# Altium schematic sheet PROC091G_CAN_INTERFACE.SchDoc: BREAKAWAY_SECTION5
size 431 x 279 mm; Date: Not shown in title block; ApprovedBy: Not shown in title block; CheckedBy: Not shown in title block; Author: Not shown in title block; CompanyName: Not shown in title block; DrawnBy: Antony/Bala; Engineer: Not shown in title block; Organization: Not shown in title block; Address1: Not shown in title block; Address2: Not shown in title block; Address3: Not shown in title block; Address4: Not shown in title block; DocumentNumber: 11; Revision: Use project parameter SCH_Rev; SheetNumber: 11; SheetTotal: 12; PageSetup: Record=PageOptions¦CenterHorizontal=True¦CenterVertical=True¦PrintScale=1.00¦XCorrection=1.00¦YCorrection=1.00¦PrintKind=0¦BorderSize=5000000¦LeftOffset=0¦BottomOffset=0¦Orientation=2¦PaperLength=1000¦PaperWidth=1000¦Scale=100¦PaperSource=15¦PrintQuality=600¦MediaType=1¦DitherType=10¦PaperKind=Letter¦PrintScaleMode=1
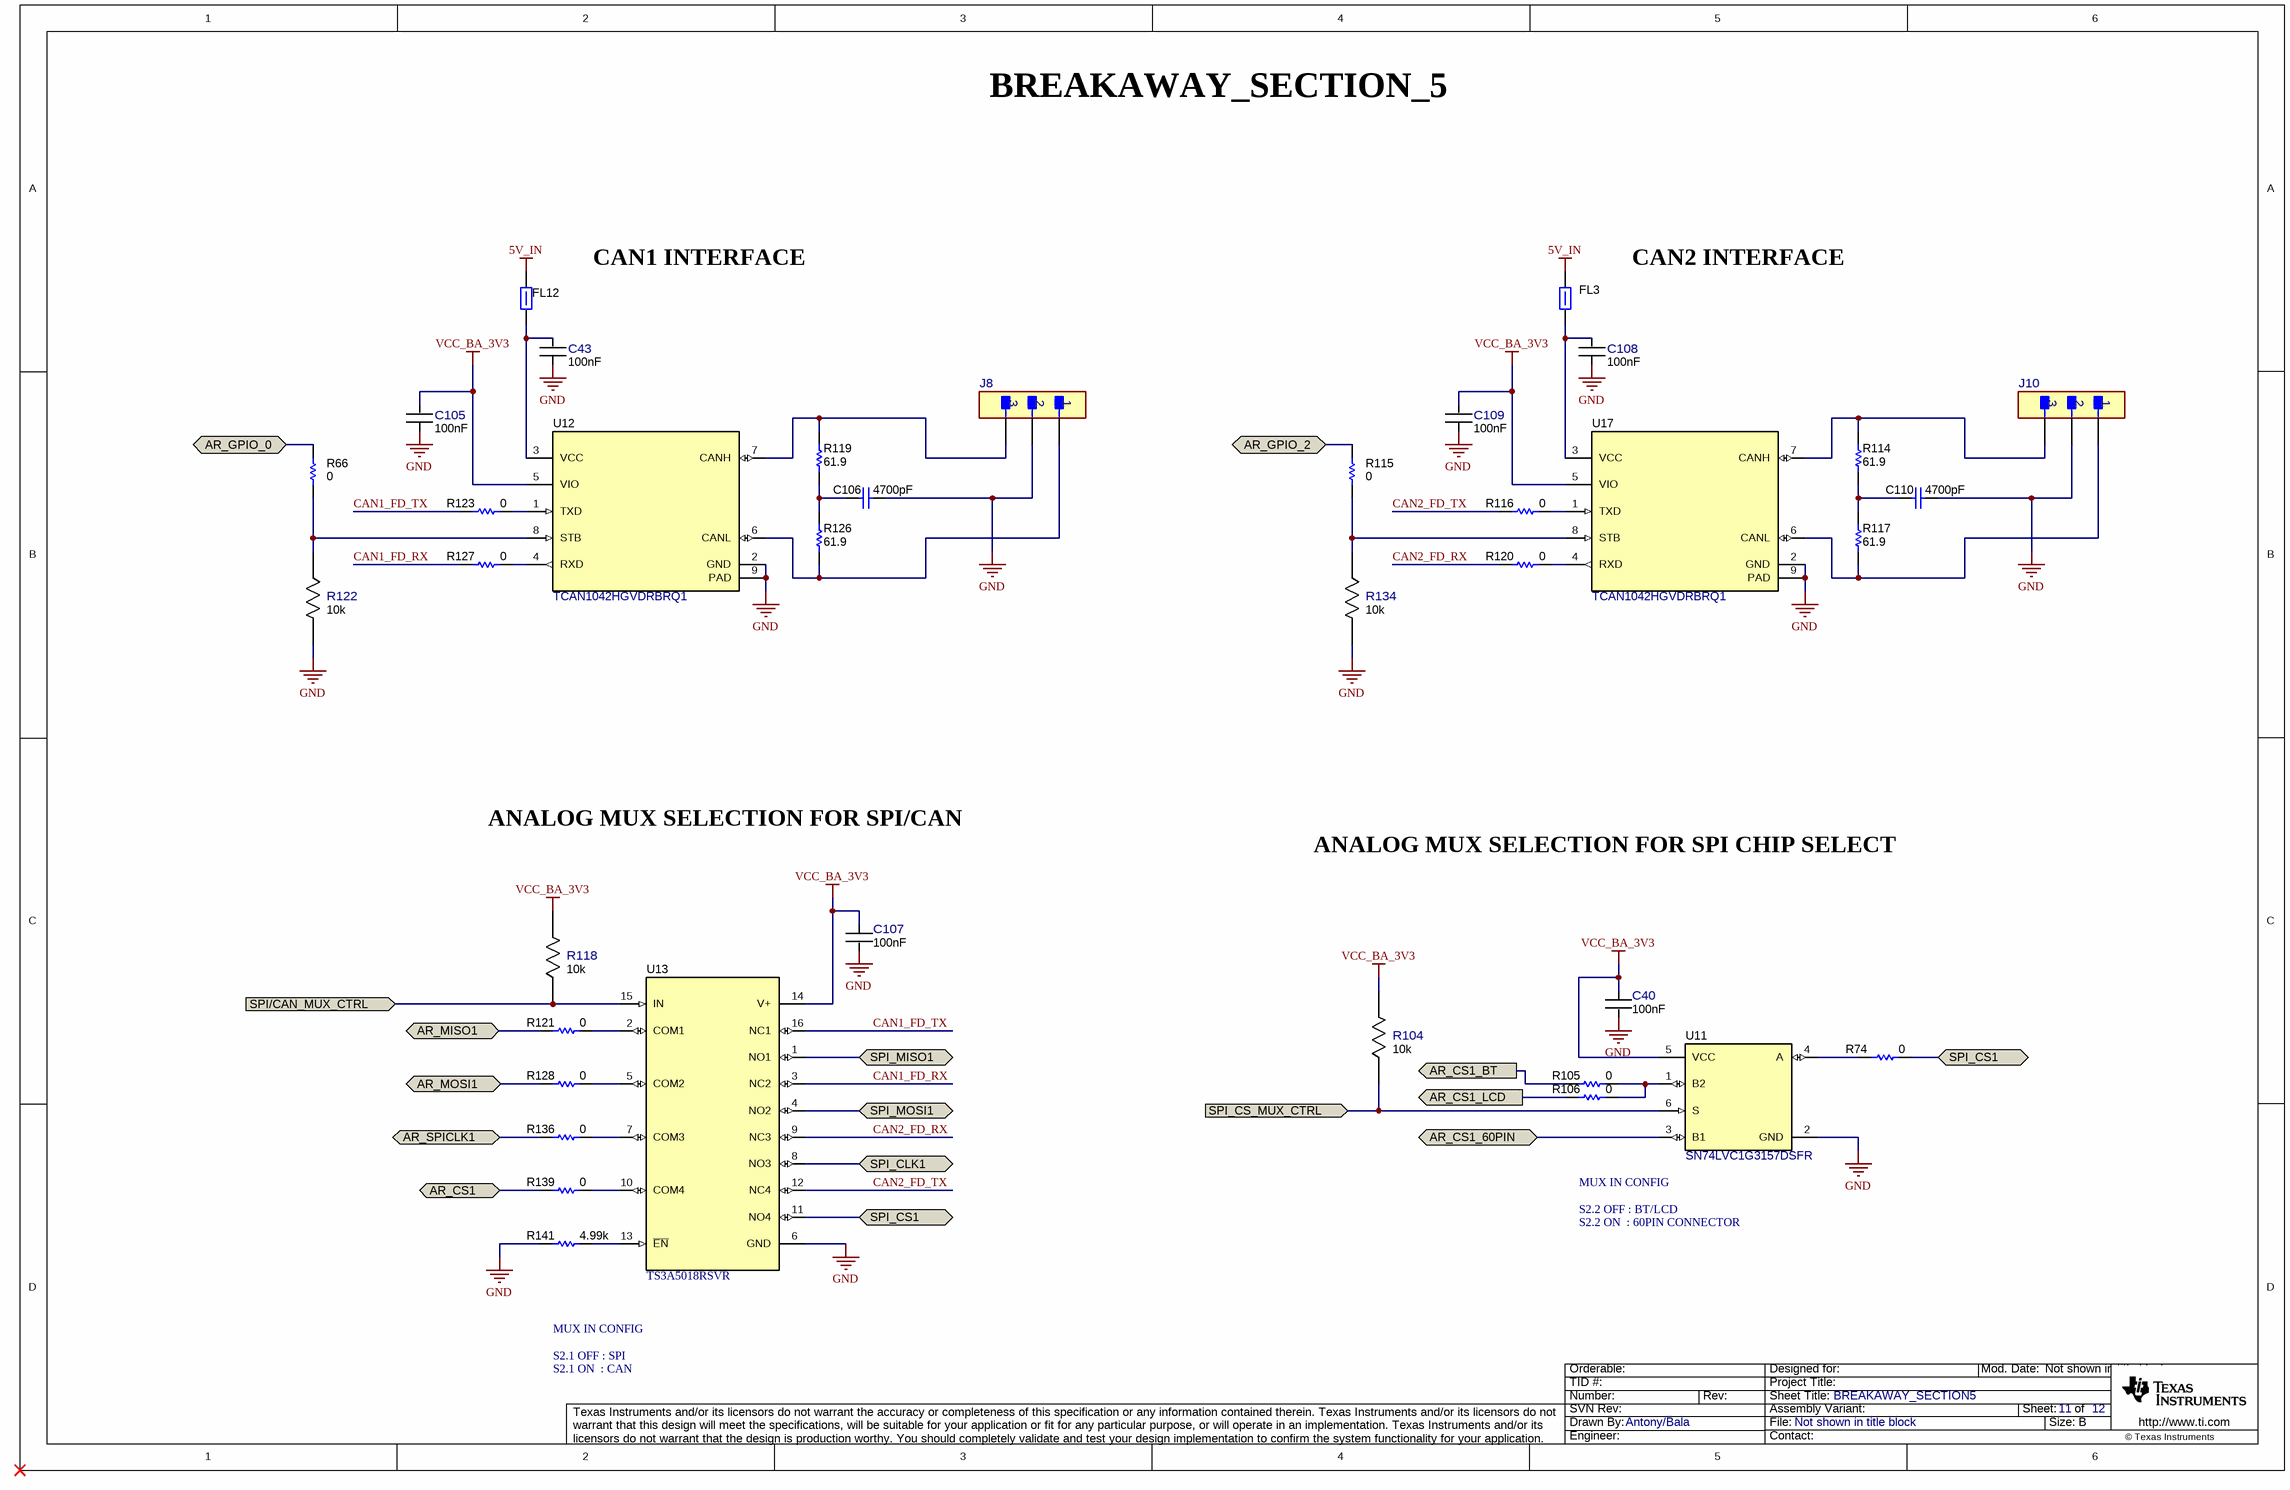
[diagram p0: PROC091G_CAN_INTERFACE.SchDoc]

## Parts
C40  Cap_F: 100nF  [FP-GRM033R6YA104KE14D_0201 (0603 Metric)-IPC_C]  (hidden comment: GRM033R6YA104KE14D)
C43  Cap_F: 100nF  [FP-GRM033R6YA104KE14D_0201 (0603 Metric)-IPC_C]  (hidden comment: GRM033R6YA104KE14D)
C105  Cap_F: 100nF  [FP-GRM033R6YA104KE14D_0201 (0603 Metric)-IPC_C]  (hidden comment: GRM033R6YA104KE14D)
C106  ValueDisplayed: 4700pF  [0402L]  (hidden comment: GRM155R71H472KA01D)
C107  Cap_F: 100nF  [FP-GRM033R6YA104KE14D_0201 (0603 Metric)-IPC_C]  (hidden comment: GRM033R6YA104KE14D)
C108  Cap_F: 100nF  [FP-GRM033R6YA104KE14D_0201 (0603 Metric)-IPC_C]  (hidden comment: GRM033R6YA104KE14D)
C109  Cap_F: 100nF  [FP-GRM033R6YA104KE14D_0201 (0603 Metric)-IPC_C]  (hidden comment: GRM033R6YA104KE14D)
C110  ValueDisplayed: 4700pF  [0402L]  (hidden comment: GRM155R71H472KA01D)
FL3  BLM15PD300SZ1D  [0402L]  (value not drawn)
FL12  BLM15PD300SZ1D  [0402L]  (value not drawn)
J8  M50-3930342  [FP-M50-3930342_HDR3-MFG]  (value not drawn)
J10  M50-3930342  [FP-M50-3930342_HDR3-MFG]  (value not drawn)
R66  Res_ohm: 0  [FP-RC0201JR-070RL_0201 (0603 Metric)-IPC_C]  (hidden comment: RC0201JR-070RL)
R74  Res_ohm: 0  [FP-RC0201JR-070RL_0201 (0603 Metric)-IPC_C]  (hidden comment: RC0201JR-070RL)
R104  Res_ohm: 10k  [FP-RR0306P-103-D_0201-IPC_C]  (hidden comment: RR0306P-103-D)
R105  Res_ohm: 0  [FP-RC0201JR-070RL_0201 (0603 Metric)-IPC_C]  (hidden comment: RC0201JR-070RL)
R106  Res_ohm: 0  [FP-RC0201JR-070RL_0201 (0603 Metric)-IPC_C]  (hidden comment: RC0201JR-070RL)
R114  ValueDisplayed: 61.9  [0402L]  (hidden comment: CRCW040261R9FKED)
R115  Res_ohm: 0  [FP-RC0201JR-070RL_0201 (0603 Metric)-IPC_C]  (hidden comment: RC0201JR-070RL)
R116  Res_ohm: 0  [FP-RC0201JR-070RL_0201 (0603 Metric)-IPC_C]  (hidden comment: RC0201JR-070RL)
R117  ValueDisplayed: 61.9  [0402L]  (hidden comment: CRCW040261R9FKED)
R118  Res_ohm: 10k  [FP-RR0306P-103-D_0201-IPC_C]  (hidden comment: RR0306P-103-D)
R119  ValueDisplayed: 61.9  [0402L]  (hidden comment: CRCW040261R9FKED)
R120  Res_ohm: 0  [FP-RC0201JR-070RL_0201 (0603 Metric)-IPC_C]  (hidden comment: RC0201JR-070RL)
R121  Res_ohm: 0  [FP-RC0201JR-070RL_0201 (0603 Metric)-IPC_C]  (hidden comment: RC0201JR-070RL)
R122  Res_ohm: 10k  [FP-RR0306P-103-D_0201-IPC_C]  (hidden comment: RR0306P-103-D)
R123  Res_ohm: 0  [FP-RC0201JR-070RL_0201 (0603 Metric)-IPC_C]  (hidden comment: RC0201JR-070RL)
R126  ValueDisplayed: 61.9  [0402L]  (hidden comment: CRCW040261R9FKED)
R127  Res_ohm: 0  [FP-RC0201JR-070RL_0201 (0603 Metric)-IPC_C]  (hidden comment: RC0201JR-070RL)
R128  Res_ohm: 0  [FP-RC0201JR-070RL_0201 (0603 Metric)-IPC_C]  (hidden comment: RC0201JR-070RL)
R134  Res_ohm: 10k  [FP-RR0306P-103-D_0201-IPC_C]  (hidden comment: RR0306P-103-D)
R136  Res_ohm: 0  [FP-RC0201JR-070RL_0201 (0603 Metric)-IPC_C]  (hidden comment: RC0201JR-070RL)
R139  Res_ohm: 0  [FP-RC0201JR-070RL_0201 (0603 Metric)-IPC_C]  (hidden comment: RC0201JR-070RL)
R141  value 4.99k  [0201L]  (hidden comment: RC0201FR-074K99L)
U11  SN74LVC1G3157DSFR  [DSF0006A]
U12  TCAN1042HGVDRBRQ1  [DRB0008F]
U13  TS3A5018RSVR  [RSV0016A]
U17  TCAN1042HGVDRBRQ1  [DRB0008F]

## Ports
AR_CS1 (bidir), AR_CS1_60PIN (bidir), AR_CS1_BT (out), AR_CS1_LCD (out), AR_GPIO_0 (bidir), AR_GPIO_2 (bidir), AR_MISO1 (bidir), AR_MOSI1 (bidir), AR_SPICLK1 (bidir), SPI/CAN_MUX_CTRL (in), SPI_CLK1 (bidir), SPI_CS1 (bidir), SPI_CS_MUX_CTRL (in), SPI_MISO1 (bidir), SPI_MOSI1 (bidir)

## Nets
5V_IN: FL3.2 FL12.2
GND: C40.2 C43.1 C105.1 C106.1 C107.2 C108.1 C109.1 C110.1 J8.2 J10.2 R122.2 R134.2 R141.2 U11.2(GND) U12.2(GND) U12.9(PAD) U13.6(GND) U17.2(GND) U17.9(PAD)
VCC_BA_3V3: C40.1 C105.2 C107.1 C109.2 R104.2 R118.2 U11.5(VCC) U12.5(VIO) U13.14(V+) U17.5(VIO)
AR_CS1: R139.2 ; port AR_CS1
AR_CS1_60PIN: U11.3(B1) ; port AR_CS1_60PIN
AR_CS1_BT: R105.2 ; port AR_CS1_BT
AR_CS1_LCD: R106.2 ; port AR_CS1_LCD
AR_GPIO_0: R66.1 ; port AR_GPIO_0
AR_GPIO_2: R115.1 ; port AR_GPIO_2
AR_MISO1: R121.2 ; port AR_MISO1
AR_MOSI1: R128.2 ; port AR_MOSI1
AR_SPICLK1: R136.2 ; port AR_SPICLK1
CAN1_FD_RX: R127.2 U13.3(NC2)
CAN1_FD_TX: R123.2 U13.16(NC1)
CAN2_FD_RX: R120.2 U13.9(NC3)
CAN2_FD_TX: R116.2 U13.12(NC4)
SPI/CAN_MUX_CTRL: R118.1 U13.15(IN) ; port SPI/CAN_MUX_CTRL
SPI_CLK1: U13.8(NO3) ; port SPI_CLK1
SPI_CS1: R74.1 U13.11(NO4) ; port SPI_CS1
SPI_CS_MUX_CTRL: R104.1 U11.6(S) ; port SPI_CS_MUX_CTRL
SPI_MISO1: U13.1(NO1) ; port SPI_MISO1
SPI_MOSI1: U13.4(NO2) ; port SPI_MOSI1
NetC43_2: C43.2 FL12.1 U12.3(VCC)
NetC106_2: C106.2 R119.1 R126.2
NetC108_2: C108.2 FL3.1 U17.3(VCC)
NetC110_2: C110.2 R114.1 R117.2
NetJ8_1: J8.1 R126.1 U12.6(CANL)
NetJ8_3: J8.3 R119.2 U12.7(CANH)
NetJ10_1: J10.1 R117.1 U17.6(CANL)
NetJ10_3: J10.3 R114.2 U17.7(CANH)
NetR66_2: R66.2 R122.1 U12.8(STB)
NetR74_2: R74.2 U11.4(A)
NetR105_1: R105.1 R106.1 U11.1(B2)
NetR115_2: R115.2 R134.1 U17.8(STB)
NetR116_1: R116.1 U17.1(TXD)
NetR120_1: R120.1 U17.4(RXD)
NetR121_1: R121.1 U13.2(COM1)
NetR123_1: R123.1 U12.1(TXD)
NetR127_1: R127.1 U12.4(RXD)
NetR128_1: R128.1 U13.5(COM2)
NetR136_1: R136.1 U13.7(COM3)
NetR139_1: R139.1 U13.10(COM4)
NetR141_1: R141.1 U13.13(~{EN})

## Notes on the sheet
- BREAKAWAY_SECTION_5
- CAN1 INTERFACE
- CAN2 INTERFACE
- ANALOG MUX SELECTION FOR SPI/CAN
- ANALOG MUX SELECTION FOR SPI CHIP SELECT
- (near U11) MUX IN CONFIG
- S2.2 ON  : 60PIN CONNECTOR
- S2.2 OFF : BT/LCD
- MUX IN CONFIG
- S2.1 OFF : SPI
- S2.1 ON  : CAN

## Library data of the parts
C40 C43 C105 C107-C109 = CMP-0086440-1: Cap Ceramic 0.1uF 35V X5R 10% Pad SMD 0201 85C T/R; Manufacturer: Murata Electronics North America; AEC Qualified: No; SizeZ_mm: 0.33mm; Symbol Name: SYM-GRM033R6YA104KE14D; TempCo: 15%
C106 C110 = CMP-0006692-2: CAP, CERM, 4700 pF, 50 V, +/- 10%, X7R, 0402; Manufacturer: MuRata; TaMin_C: -55°C; Polarized: N; SizeAreaWB_mm2: 3; Value1: Unknown; U/M: EA; Value: 4700pF; TaMax_C: 125°C; SizeZ_mm: 0.6; SizeX_mm: 1; SizeY_mm: 0.5; Cap_Case: 0402; Value2: 50V; Cap_F: 4.7nF; AEC Category: Q200
FL3 FL12 = CMP-0078934-1: Inductor, Ferrite Bead, Ferrite, 2.2 A, 0.035 ohm, AEC-Q200 Grade 1, SMD; Manufacturer: MuRata; AEC Category: Q200; AEC Grade: 1; AEC Qualified: Y; DCR_ohm: 0.035; Imax_A: 2.2A; SizeArea_mm2: 0.5; SizeAreaWB_mm2: 3; SizeZ_mm: 0.6
J8 J10 = CMP-0087785-1: CONN HEADER R/A 3POS 1.27MM; Manufacturer: Harwin; Row_Count: 1; Current_A: 1A; ContactFinish: Gold,Nickel
R66 R74 R105 R106 R115 R116 R120 R121 R123 R127 R128 R136 R139 = CMP-0086442-2: RES SMD 0 OHM JUMPER 1/20W 0201; Manufacturer: Yageo; AEC Qualified: No; Power_W: 50mW; SizeZ_mm: 0.26mm; TempCo: 200ppm/°C; Tolerance_%: 5%; VDC_V: 25V
R104 R118 R122 R134 = CMP-0088002-1: 10 kOhms ±0.5% 0.05W, 1/20W Chip Resistor 0201 (0603 Metric)  Thin Film; Manufacturer: Susumu; AEC Qualified: No; Power_W: 50mW; SizeZ_mm: 0.26mm; Symbol Name: SYM-RR0306P-103-D; TempCo: 25ppm/°C; VDC_V: 15V
R114 R117 R119 R126 = CMP-0026491-2: RES, 61.9, 1%, 0.063 W, AEC-Q200 Grade 0, 0402; Manufacturer: Vishay-Dale; Power_W: 63mW; TempCo: 100 ppm/C; Value_Code: 61R9; Value: 61.9; EIA_Code: E96; SizeX_mm: 1; SizeY_mm: 0.5; SizeZ_mm: 0.6; Value2: 0.063W; AEC Qualified: Y; VDC_V: 50V; AEC Category: Q200; AEC Grade: 0
R141 = CMP-0027745-1: RES, 4.99 k, 1%, 0.05 W, 0201; Manufacturer: Yageo America; AEC Category: Q200; AEC Qualified: N; EIA_Code: E96; Power_W: 50mW; SizeArea_mm2: 0.18; SizeX_mm: 0.6; SizeY_mm: 0.3; SizeZ_mm: 0.26; TempCo: 200 ppm/C; U/M: EA; Value2: 0.05W; Value_Code: 4k99; VDC_V: 25V
U11 = CMP-0050992-5: 1-Channel, 2:1 Analog Switch, DSF0006A (X2SON-6); Manufacturer: Texas Instruments; 3-State Output: No; AEC Category: Q200; AEC Qualified: N; Bits(#): 1; CompType: IC; F @ Nom Voltage(Max)(Mhz): 150; ICC @ Nom Voltage(Max)(mA): 0.01; Input Type: CMOS/TTL; Logic: True; Mux Configuration: 1：2; Output Drive (IOL/IOH)(Max)(mA): 32/-32; Output Type: CMOS; Rating: Catalog; Switch Configuration: SPDT; Technology Family: LVC; tpd @ Nom Voltage(Max)(ns): 2,1.2,0.8,0.3; VCC(Max)(V): 5.5; VCC(Min)(V): 1.65; Voltage(Nom)(V): 1.8,2.5,3.3,5
U12 U17 = CMP-0065183-3: Automotive Fault Protected CAN Transceiver With Flexible Data-Rate, DRB0008F (VSON-8); Manufacturer: Texas Instruments; Alternate PartNumber: TCAN1042HGVDRBTQ1; SizeX_mm: 3.0; CompType: IC; SizeZ_mm: 1.0; SizeArea_mm2: 9.0; SizeAreaWB_mm2: 16.0; AEC Category: Q200; AEC Qualified: Y
U13 = CMP-0067415-1: 10-Ohm Quad SPDT Analog Switch, RSV0016A (UQFN-16); Alternate Manufacturer: Texas Instruments; SizeAreaWB_mm2: 10.08; U/M: EA; SizeZ_mm: 0.55; SizeX_mm: 1.8; SizeY_mm: 2.6; SizeArea_mm2: 4.68; CompType: IC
